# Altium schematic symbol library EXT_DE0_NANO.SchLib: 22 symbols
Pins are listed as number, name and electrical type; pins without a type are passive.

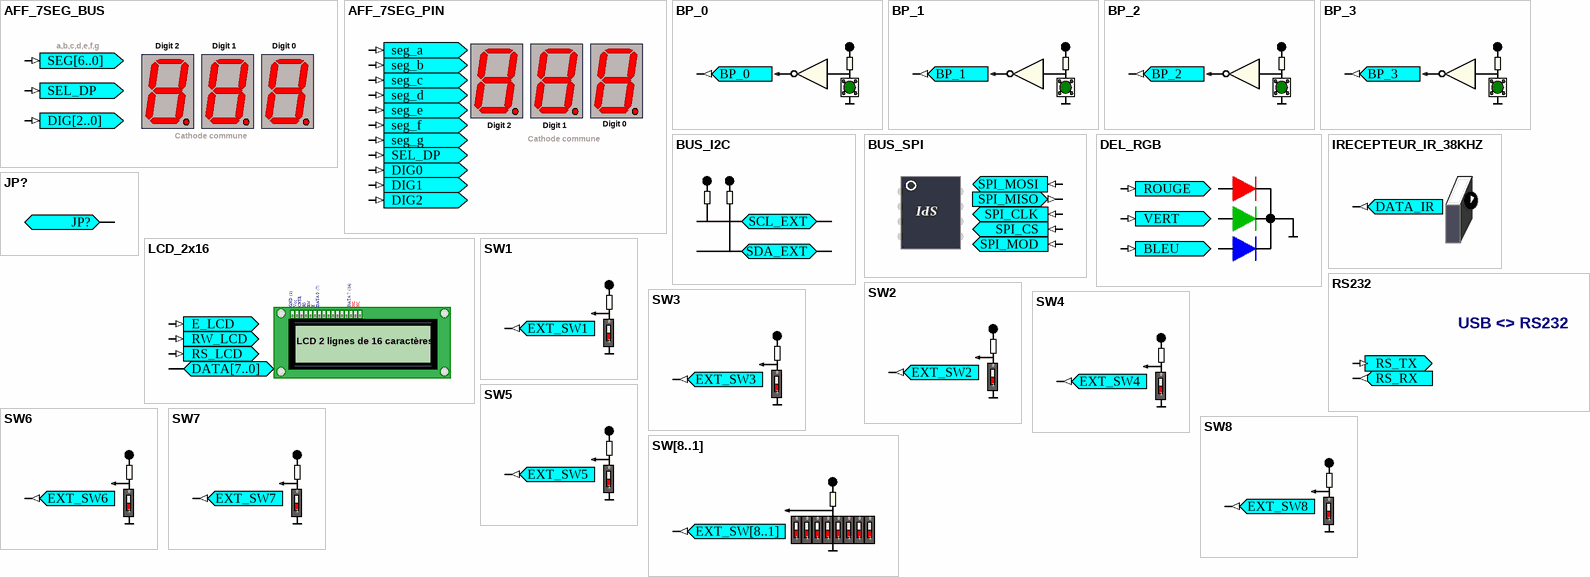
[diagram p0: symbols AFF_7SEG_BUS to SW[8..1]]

## AFF_7SEG_BUS
designator 7SEG, comment 7SEG  (value not drawn)
Afficheur 7 Segments; PortComponent: True
pins: DIG[2..0] (in), SEG[6..0] (in), SEL_DP (in)

## AFF_7SEG_PIN
designator 7SEG, comment 7SEG  (value not drawn)
Afficheur 7 Segments; PortComponent: True
pins: DIG0 (in), DIG1 (in), DIG2 (in), seg_a (in), seg_b (in), seg_c (in), seg_d (in), seg_e (in), seg_f (in), seg_g (in), SEL_DP (in)

## BP_0
designator ?
Bouton poussoir (NL 1 au repos); PortComponent: True
pins: BP_0 (out)

## BP_1
designator ?
Bouton poussoir (NL 1 au repos); PortComponent: True
pins: BP_1 (out)

## BP_2
designator ?
Bouton poussoir (NL 1 au repos); PortComponent: True
pins: BP_2 (out)

## BP_3
designator ?
Bouton poussoir (NL 1 au repos); PortComponent: True
pins: BP_3 (out)

## BUS_I2C
designator ?  (value not drawn)
I2C Bus Interface; PortComponent: True
pins: SCL_EXT (io), SDA_EXT (io)

## BUS_SPI
designator BUS_SPI  (value not drawn)
pins: SPI_CLK (in), SPI_CS (in), SPI_MISO (out), SPI_MOD (in), SPI_MOSI (in)

## DEL_RGB
designator ?
Diode RGB; PortComponent: True
pins: BLEU (in), ROUGE (in), VERT (in)

## IRECEPTEUR_IR_38KHZ
designator ?
Recepteur Infra rouge; PortComponent: True
pins: DATA_IR (out)

## JP?
designator ?
Pin connecteur; PortComponent: True
pins: JP? (io)

## LCD_2x16
designator ?, comment LCD_2x16_1  (value not drawn)
Liquid Crystal Display; PortComponent: True
pins: DATA[7..0] (io), E_LCD (in), RS_LCD (in), RW_LCD (in)

## RS232
designator ?, comment RS232CNTR  (value not drawn)
Convertisseur USB_RS232; PortComponent: True
pins: RS_RX (out), RS_TX (in)

## SW1
designator ?
Generic User Buttons; PortComponent: True
pins: EXT_SW1 (out)

## SW2
designator ?
Generic User Buttons; PortComponent: True
pins: EXT_SW2 (out)

## SW3
designator ?
Generic User Buttons; PortComponent: True
pins: EXT_SW3 (out)

## SW4
designator ?
Generic User Buttons; PortComponent: True
pins: EXT_SW4 (out)

## SW5
designator ?
Generic User Buttons; PortComponent: True
pins: EXT_SW5 (out)

## SW6
designator ?
Generic User Buttons; PortComponent: True
pins: EXT_SW6 (out)

## SW7
designator ?
Generic User Buttons; PortComponent: True
pins: EXT_SW7 (out)

## SW8
designator ?
Generic User Buttons; PortComponent: True
pins: EXT_SW8 (out)

## SW[8..1]
designator ?
Generic User Buttons; PortComponent: True
pins: EXT_SW[8..1] (out)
